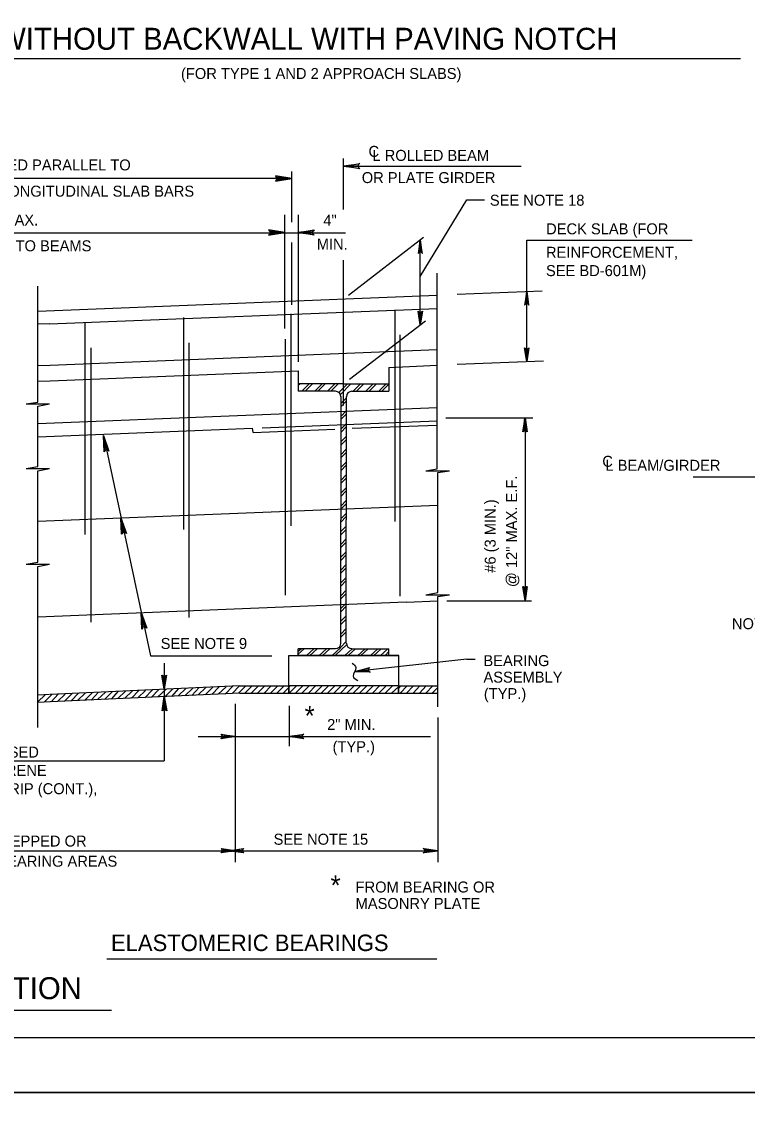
# Model space of a CAD drawing. Extents: x 640009 to 641706, y 298547 to 299735.
# Drawn here: x 640263.3 to 640461.6, y 299133.7 to 299433.7 of the extents above; entities that cross this region are included whole.
import ezdxf

# ---------------------------------------------------------------- set-up
doc = ezdxf.new("R2010")
doc.units = 0
doc.layers.add('1', color=7, linetype='Continuous')
doc.layers.add('PLT-BNDY', color=7, linetype='Continuous')

msp = doc.modelspace()

# ---------------------------------------------------------------- linework, layer by layer
at = {"layer": '1'}
for p, q in [((640254.55, 299423.68), (640459.83, 299423.68)), ((640351.28, 299382.42), (640351.28, 299396.36)), ((640337.03, 299392.84), (640337.03, 299379)), ((640351.28, 299394.31), (640399.81, 299394.31)), ((640191.28, 299390.99), (640337.03, 299390.99)), ((640372.25, 299364.12), (640385.01, 299385.07)), ((640385.01, 299385.07), (640389.78, 299385.07)), ((640335.15, 299380.98), (640335.15, 299349.93)), ((640338.9, 299380.98), (640338.9, 299340.83)), ((640169.89, 299376.11), (640351.8, 299376.11)), ((640352.59, 299359.04), (640373.15, 299374.87)), ((640337.03, 299373.39), (640337.03, 299356.43)), ((640372.25, 299350.95), (640372.25, 299374.18)), ((640401.37, 299340.91), (640401.37, 299374.09)), ((640401.37, 299374.09), (640446.57, 299374.09)), ((640351.28, 299328.92), (640351.28, 299368.63)), ((640376.9, 299311.56), (640376.9, 299365.06)), ((640267.65, 299329.83), (640267.65, 299361.46)), ((640382.39, 299359.28), (640405.63, 299360.21)), ((640267.65, 299354.68), (640376.9, 299359.06)), ((640270.9, 299351.18), (640376.9, 299355.43)), ((640336.9, 299353.93), (640336.9, 299296.06)), ((640365.28, 299355.06), (640365.28, 299297.18)), ((640267.65, 299351.18), (640270.9, 299351.31)), ((640280.53, 299351.56), (640280.53, 299293.68)), ((640307.53, 299352.93), (640307.53, 299295.06)), ((640352.94, 299336.09), (640373.66, 299352.03)), ((640366.78, 299276.81), (640366.78, 299348.18)), ((640282.28, 299269.68), (640282.28, 299344.68)), ((640309.03, 299270.93), (640309.03, 299346.06)), ((640335.4, 299277.06), (640335.4, 299347.06)), ((640271.03, 299339.93), (640376.9, 299344.18)), ((640267.65, 299339.8), (640271.03, 299339.93)), ((640271.03, 299335.68), (640338.9, 299338.4)), ((640338.9, 299338.4), (640338.9, 299332.81)), ((640363.65, 299339.32), (640376.9, 299339.93)), ((640363.65, 299339.32), (640363.65, 299332.81)), ((640382.39, 299340.15), (640405.99, 299341.1)), ((640267.65, 299335.55), (640271.03, 299335.68)), ((640351.28, 299334.81), (640338.9, 299334.81)), ((640351.28, 299334.81), (640338.9, 299334.81)), ((640338.9, 299334.81), (640338.9, 299333.81)), ((640351.28, 299334.81), (640338.9, 299334.81)), ((640338.9, 299334.81), (640338.9, 299332.81)), ((640349.03, 299332.81), (640338.9, 299332.81)), ((640349.03, 299332.81), (640338.9, 299332.81)), ((640351.28, 299334.81), (640363.65, 299334.81)), ((640351.28, 299334.81), (640363.65, 299334.81)), ((640351.28, 299334.81), (640363.65, 299334.81)), ((640353.53, 299332.81), (640363.65, 299332.81)), ((640353.53, 299332.81), (640363.65, 299332.81)), ((640363.65, 299334.81), (640363.65, 299333.81)), ((640363.65, 299334.81), (640363.65, 299332.81)), ((640264.53, 299329.33), (640267.65, 299329.83)), ((640264.53, 299329.33), (640270.9, 299329.33)), ((640267.65, 299328.68), (640270.9, 299329.33)), ((640267.78, 299329.33), (640267.78, 299329.33)), ((640350.53, 299331.31), (640350.53, 299297.68)), ((640350.53, 299331.31), (640350.53, 299297.68)), ((640352.03, 299331.31), (640352.03, 299297.68)), ((640352.03, 299331.31), (640352.03, 299297.68)), ((640267.65, 299320.36), (640267.65, 299328.68)), ((640267.65, 299323.98), (640376.9, 299328.36)), ((640329.03, 299322.81), (640376.9, 299324.68)), ((640353.65, 299322.68), (640376.9, 299323.56)), ((640379.28, 299325.56), (640403.03, 299325.56)), ((640400.9, 299325.56), (640400.9, 299275.56)), ((640267.65, 299320.36), (640326.4, 299322.68)), ((640267.65, 299312.19), (640267.65, 299320.36)), ((640285.61, 299320.74), (640298.47, 299260.46)), ((640326.53, 299321.56), (640326.4, 299322.68)), ((640326.53, 299321.56), (640348.9, 299322.43)), ((640264.53, 299311.69), (640267.65, 299312.19)), ((640264.53, 299311.69), (640270.9, 299311.69)), ((640267.65, 299311.04), (640270.9, 299311.69)), ((640267.78, 299311.69), (640267.78, 299311.69)), ((640373.78, 299311.06), (640376.9, 299311.56)), ((640267.65, 299286.06), (640267.65, 299311.04)), ((640373.78, 299311.06), (640380.28, 299311.06)), ((640377.03, 299310.56), (640380.28, 299311.06)), ((640377.03, 299311.06), (640377.03, 299311.06)), ((640377.03, 299277.81), (640377.03, 299310.56)), ((640446.9, 299309.42), (640496.46, 299309.42)), ((640267.65, 299297.33), (640377.03, 299301.68)), ((640350.53, 299263.93), (640350.53, 299297.68)), ((640350.53, 299263.93), (640350.53, 299297.68)), ((640352.03, 299263.93), (640352.03, 299297.68)), ((640352.03, 299263.93), (640352.03, 299297.68)), ((640264.53, 299285.56), (640267.65, 299286.06)), ((640264.53, 299285.56), (640270.9, 299285.56)), ((640267.65, 299284.91), (640270.9, 299285.56)), ((640267.65, 299240.93), (640267.65, 299284.91)), ((640267.78, 299285.56), (640267.78, 299285.56)), ((640267.65, 299271.18), (640368.4, 299275.25)), ((640368.4, 299275.18), (640377.03, 299275.56)), ((640373.78, 299277.18), (640377.03, 299277.81)), ((640373.78, 299277.18), (640380.28, 299277.18)), ((640377.03, 299276.68), (640380.28, 299277.18)), ((640377.03, 299246.56), (640377.03, 299276.68)), ((640379.53, 299275.56), (640402.65, 299275.56)), ((640298.47, 299260.46), (640331.68, 299260.46)), ((640336.28, 299250.31), (640336.28, 299260.56)), ((640336.28, 299260.56), (640366.4, 299260.56)), ((640349.03, 299262.43), (640338.9, 299262.43)), ((640338.9, 299260.56), (640338.9, 299262.43)), ((640349.03, 299262.43), (640338.9, 299262.43)), ((640338.9, 299260.56), (640338.9, 299262.43)), ((640366.4, 299260.56), (640338.9, 299260.56)), ((640351.28, 299260.56), (640338.9, 299260.56)), ((640351.28, 299260.56), (640363.65, 299260.56)), ((640353.53, 299262.43), (640363.65, 299262.43)), ((640353.53, 299262.43), (640363.65, 299262.43)), ((640363.65, 299260.56), (640363.65, 299262.43)), ((640363.65, 299260.56), (640363.65, 299262.43)), ((640366.4, 299250.31), (640366.4, 299260.56)), ((640302.25, 299258.47), (640302.25, 299231.8)), ((640385.03, 299259.56), (640354.54, 299256.23)), ((640385.03, 299259.56), (640387.28, 299259.56)), ((640322.78, 299252.31), (640271.03, 299249.93)), ((640322.9, 299252.31), (640336.28, 299252.31)), ((640366.4, 299252.31), (640376.9, 299252.31)), ((640270.9, 299249.93), (640267.65, 299249.79)), ((640322.9, 299250.31), (640271.03, 299247.93)), ((640322.9, 299250.31), (640336.28, 299250.31)), ((640336.28, 299250.31), (640366.4, 299250.31)), ((640336.28, 299250.31), (640366.28, 299250.31)), ((640366.4, 299250.31), (640376.9, 299250.31)), ((640271.03, 299247.93), (640267.65, 299247.78)), ((640321.65, 299247.43), (640321.65, 299204.09)), ((640336.4, 299246.81), (640336.4, 299235.81)), ((640377.03, 299243.68), (640377.03, 299204.09)), ((640311.53, 299238.43), (640339.15, 299238.43)), ((640336.15, 299238.43), (640375.04, 299238.43)), ((640227.64, 299231.8), (640302.25, 299231.8)), ((640200.03, 299207.26), (640321.65, 299207.26)), ((640321.65, 299207.26), (640377.03, 299207.26)), ((640286.55, 299177.75), (640376.81, 299177.75)), ((640232.63, 299163.7), (640287.78, 299163.7)), ((640835.47, 299156.17), (640049.47, 299156.17)), ((640835.47, 299156.17), (640049.47, 299156.17))]:
    msp.add_line(p, q, dxfattribs=at)
for points in [[(640355.52, 299393.77), (640355.35, 299394.09), (640351.28, 299394.31), (640355.52, 299393.77), (640355.73, 299393.58), (640351.28, 299394.31), (640355.35, 299394.51), (640355.5, 299394.81), (640351.28, 299394.31), (640355.73, 299395.03), (640355.5, 299394.81)], [(640332.86, 299390.34), (640333.04, 299390.66), (640337.11, 299390.88), (640332.86, 299390.34), (640332.65, 299390.16), (640337.11, 299390.88), (640333.04, 299391.08), (640332.88, 299391.38), (640337.11, 299390.88), (640332.65, 299391.61), (640332.88, 299391.38)], [(640330.99, 299375.59), (640331.16, 299375.91), (640335.23, 299376.13), (640330.99, 299375.59), (640330.78, 299375.41), (640335.23, 299376.13), (640331.16, 299376.33), (640331.01, 299376.63), (640335.23, 299376.13), (640330.78, 299376.86), (640331.01, 299376.63)], [(640343.07, 299375.59), (640342.89, 299375.91), (640338.82, 299376.13), (640343.07, 299375.59), (640343.28, 299375.41), (640338.82, 299376.13), (640342.89, 299376.33), (640343.05, 299376.63), (640338.82, 299376.13), (640343.28, 299376.86), (640343.05, 299376.63)], [(640372.7, 299370.64), (640372.44, 299370.79), (640372.25, 299374.18), (640372.7, 299370.64), (640372.86, 299370.46), (640372.25, 299374.18), (640372.09, 299370.79), (640371.84, 299370.65), (640372.25, 299374.18), (640371.65, 299370.46), (640371.84, 299370.65)], [(640401.82, 299356.5), (640401.56, 299356.65), (640401.37, 299360.04), (640401.82, 299356.5), (640401.98, 299356.33), (640401.37, 299360.04), (640401.21, 299356.65), (640400.95, 299356.52), (640401.37, 299360.04), (640400.77, 299356.33), (640400.95, 299356.52)], [(640372.7, 299354.49), (640372.44, 299354.34), (640372.25, 299350.95), (640372.7, 299354.49), (640372.86, 299354.67), (640372.25, 299350.95), (640372.09, 299354.34), (640371.84, 299354.48), (640372.25, 299350.95), (640371.65, 299354.67), (640371.84, 299354.48)], [(640401.82, 299344.45), (640401.56, 299344.3), (640401.37, 299340.91), (640401.82, 299344.45), (640401.98, 299344.62), (640401.37, 299340.91), (640401.21, 299344.3), (640400.95, 299344.43), (640401.37, 299340.91), (640400.77, 299344.62), (640400.95, 299344.43)], [(640338.9, 299334.43), (640339.28, 299334.81)], [(640339.9, 299332.81), (640341.9, 299334.81)], [(640340.78, 299332.81), (640342.78, 299334.81)], [(640343.4, 299332.81), (640345.4, 299334.81)], [(640344.28, 299332.81), (640346.28, 299334.81)], [(640346.9, 299332.81), (640348.9, 299334.81)], [(640347.78, 299332.81), (640349.78, 299334.81)], [(640350.03, 299332.43), (640352.4, 299334.81)], [(640350.4, 299331.93), (640353.28, 299334.81)], [(640353.9, 299332.81), (640355.9, 299334.81)], [(640354.78, 299332.81), (640356.78, 299334.81)], [(640357.4, 299332.81), (640359.4, 299334.81)], [(640358.28, 299332.81), (640360.28, 299334.81)], [(640360.9, 299332.81), (640362.9, 299334.81)], [(640361.78, 299332.81), (640363.65, 299334.68)], [(640363.53, 299332.81), (640363.65, 299332.93)], [(640350.53, 299329.43), (640352.03, 299330.93)], [(640350.53, 299328.56), (640352.03, 299330.06)], [(640350.53, 299325.93), (640352.03, 299327.43)], [(640350.53, 299325.06), (640352.03, 299326.56)], [(640350.53, 299322.43), (640352.03, 299323.93)], [(640400.4, 299321.81), (640400.78, 299321.93), (640400.9, 299325.56), (640400.4, 299321.81), (640400.28, 299321.68), (640400.9, 299325.56), (640401.15, 299321.93), (640401.4, 299321.81), (640400.9, 299325.56), (640401.53, 299321.68), (640401.4, 299321.81)], [(640401.34, 299321.98), (640401.07, 299322.13), (640400.89, 299325.52), (640401.34, 299321.98), (640401.49, 299321.81), (640400.89, 299325.52), (640400.72, 299322.13), (640400.47, 299322), (640400.89, 299325.52), (640400.29, 299321.81), (640400.47, 299322)], [(640285.99, 299316.43), (640286.18, 299316.61), (640285.61, 299320.74), (640285.99, 299316.43), (640285.8, 299316.24), (640285.61, 299320.74), (640286.55, 299316.8), (640286.93, 299316.61), (640285.61, 299320.74), (640287.11, 299316.43), (640286.93, 299316.61)], [(640350.53, 299321.56), (640352.03, 299323.06)], [(640350.53, 299318.93), (640352.03, 299320.43)], [(640350.53, 299318.06), (640352.03, 299319.56)], [(640350.53, 299315.43), (640352.03, 299316.93)], [(640350.53, 299314.56), (640352.03, 299316.06)], [(640350.53, 299311.93), (640352.03, 299313.43)], [(640350.53, 299311.06), (640352.03, 299312.56)], [(640350.53, 299308.43), (640352.03, 299309.93)], [(640350.53, 299307.56), (640352.03, 299309.06)], [(640350.53, 299304.93), (640352.03, 299306.43)], [(640350.53, 299304.06), (640352.03, 299305.56)], [(640350.53, 299301.43), (640352.03, 299302.93)], [(640350.53, 299300.56), (640352.03, 299302.06)], [(640350.53, 299297.93), (640352.03, 299299.43)], [(640290.78, 299293.92), (640290.97, 299294.11), (640290.41, 299298.24), (640290.78, 299293.92), (640290.6, 299293.74), (640290.41, 299298.24), (640291.35, 299294.3), (640291.72, 299294.11), (640290.41, 299298.24), (640291.91, 299293.92), (640291.72, 299294.11)], [(640350.53, 299297.06), (640352.03, 299298.56)], [(640350.53, 299294.43), (640352.03, 299295.93)], [(640350.53, 299293.56), (640352.03, 299295.06)], [(640350.53, 299290.93), (640352.03, 299292.43)], [(640350.53, 299290.06), (640352.03, 299291.56)], [(640350.53, 299287.43), (640352.03, 299288.93)], [(640350.53, 299286.56), (640352.03, 299288.06)], [(640350.53, 299283.93), (640352.03, 299285.43)], [(640350.53, 299283.06), (640352.03, 299284.56)], [(640350.53, 299280.43), (640352.03, 299281.93)], [(640350.53, 299279.56), (640352.03, 299281.06)], [(640350.53, 299276.93), (640352.03, 299278.43)], [(640401.4, 299279.31), (640401.15, 299279.18), (640400.9, 299275.56), (640401.4, 299279.31), (640401.53, 299279.43), (640400.9, 299275.56), (640400.78, 299279.18), (640400.53, 299279.31), (640400.9, 299275.56), (640400.28, 299279.43), (640400.53, 299279.31)], [(640350.53, 299276.06), (640352.03, 299277.56)], [(640296.32, 299268.02), (640296.5, 299268.2), (640295.94, 299272.33), (640296.32, 299268.02), (640296.13, 299267.83), (640295.94, 299272.33), (640296.88, 299268.39), (640297.25, 299268.2), (640295.94, 299272.33), (640297.44, 299268.02), (640297.25, 299268.2)], [(640350.53, 299273.43), (640352.03, 299274.93)], [(640350.53, 299272.56), (640352.03, 299274.06)], [(640350.53, 299269.93), (640352.03, 299271.43)], [(640350.53, 299269.06), (640352.03, 299270.56)], [(640350.53, 299266.43), (640352.03, 299267.93)], [(640350.53, 299265.56), (640352.03, 299267.06)], [(640349.03, 299260.56), (640352.15, 299263.56)], [(640350.4, 299262.81), (640352.03, 299264.43)], [(640338.9, 299260.93), (640340.53, 299262.43)], [(640338.9, 299261.81), (640339.65, 299262.43)], [(640341.15, 299260.56), (640343.15, 299262.43)], [(640342.03, 299260.56), (640344.03, 299262.43)], [(640344.65, 299260.56), (640346.65, 299262.43)], [(640345.53, 299260.56), (640347.53, 299262.43)], [(640348.15, 299260.56), (640350.4, 299262.68)], [(640351.65, 299260.56), (640353.65, 299262.43)], [(640352.53, 299260.56), (640354.53, 299262.43)], [(640355.15, 299260.56), (640357.15, 299262.43)], [(640356.03, 299260.56), (640358.03, 299262.43)], [(640358.65, 299260.56), (640360.65, 299262.43)], [(640359.53, 299260.56), (640361.53, 299262.43)], [(640361.4, 299260.56), (640363.4, 299262.43)], [(640362.65, 299260.56), (640363.65, 299261.68)], [(640358.29, 299256.16), (640358.19, 299256.42), (640354.54, 299256.23), (640358.29, 299256.16), (640358.53, 299256.02), (640354.54, 299256.23), (640358.1, 299256.81), (640358.25, 299257.17), (640354.54, 299256.23), (640358.39, 299257.29), (640358.25, 299257.17)], [(640302.71, 299255.12), (640302.46, 299254.99), (640302.25, 299251.36), (640302.71, 299255.12), (640302.83, 299255.25), (640302.25, 299251.36), (640302.08, 299254.99), (640301.83, 299255.11), (640302.25, 299251.36), (640301.58, 299255.23), (640301.83, 299255.11)], [(640298.78, 299249.18), (640300.78, 299251.31)], [(640300.53, 299249.31), (640302.65, 299251.31)], [(640302.4, 299249.31), (640304.53, 299251.43)], [(640304.28, 299249.43), (640306.28, 299251.56)], [(640306.03, 299249.56), (640308.15, 299251.56)], [(640307.9, 299249.56), (640310.03, 299251.68)], [(640309.78, 299249.68), (640311.78, 299251.81)], [(640311.53, 299249.81), (640313.65, 299251.81)], [(640313.4, 299249.81), (640315.53, 299251.93)], [(640315.28, 299249.93), (640317.28, 299252.06)], [(640317.03, 299250.06), (640319.15, 299252.06)], [(640318.9, 299250.06), (640321.03, 299252.18)], [(640320.78, 299250.18), (640322.78, 299252.31)], [(640322.53, 299250.31), (640324.53, 299252.31)], [(640324.28, 299250.31), (640326.28, 299252.31)], [(640326.03, 299250.31), (640328.03, 299252.31)], [(640327.78, 299250.31), (640329.78, 299252.31)], [(640329.53, 299250.31), (640331.53, 299252.31)], [(640331.28, 299250.31), (640333.28, 299252.31)], [(640333.03, 299250.31), (640335.03, 299252.31)], [(640334.78, 299250.31), (640336.28, 299251.81)], [(640336.28, 299251.93), (640336.65, 299252.31)], [(640336.4, 299250.31), (640338.4, 299252.31)], [(640338.15, 299250.31), (640340.15, 299252.31)], [(640339.9, 299250.31), (640341.9, 299252.31)], [(640341.65, 299250.31), (640343.65, 299252.31)], [(640343.4, 299250.31), (640345.4, 299252.31)], [(640345.15, 299250.31), (640347.15, 299252.31)], [(640346.9, 299250.31), (640348.9, 299252.31)], [(640348.65, 299250.31), (640350.65, 299252.31)], [(640350.4, 299250.31), (640352.4, 299252.31)], [(640352.15, 299250.31), (640354.15, 299252.31)], [(640353.9, 299250.31), (640355.9, 299252.31)], [(640355.65, 299250.31), (640357.65, 299252.31)], [(640357.4, 299250.31), (640359.4, 299252.31)], [(640359.15, 299250.31), (640361.15, 299252.31)], [(640360.9, 299250.31), (640362.9, 299252.31)], [(640362.65, 299250.31), (640364.65, 299252.31)], [(640364.4, 299250.31), (640366.28, 299252.06)], [(640366.4, 299251.68), (640366.9, 299252.31)], [(640366.78, 299250.31), (640368.65, 299252.31)], [(640368.53, 299250.31), (640370.4, 299252.31)], [(640370.28, 299250.31), (640372.15, 299252.31)], [(640372.03, 299250.31), (640373.9, 299252.31)], [(640373.78, 299250.31), (640375.65, 299252.31)], [(640375.53, 299250.31), (640376.9, 299251.68)], [(640267.65, 299247.92), (640269.65, 299249.81)], [(640267.65, 299249.67), (640267.78, 299249.81)], [(640269.4, 299247.81), (640271.53, 299249.93)], [(640271.28, 299247.93), (640273.28, 299250.06)], [(640273.03, 299248.06), (640275.15, 299250.06)], [(640274.9, 299248.06), (640277.03, 299250.18)], [(640276.78, 299248.18), (640278.78, 299250.31)], [(640278.53, 299248.31), (640280.65, 299250.31)], [(640280.4, 299248.31), (640282.53, 299250.43)], [(640282.28, 299248.43), (640284.28, 299250.56)], [(640284.03, 299248.56), (640286.15, 299250.56)], [(640285.9, 299248.56), (640288.03, 299250.68)], [(640287.78, 299248.68), (640289.78, 299250.81)], [(640289.53, 299248.81), (640291.65, 299250.81)], [(640291.4, 299248.81), (640293.53, 299250.93)], [(640293.28, 299248.93), (640295.28, 299251.06)], [(640295.03, 299249.06), (640297.15, 299251.06)], [(640296.9, 299249.06), (640299.03, 299251.18)], [(640301.83, 299245.6), (640302.07, 299245.73), (640302.25, 299249.36), (640301.83, 299245.6), (640301.7, 299245.47), (640302.25, 299249.36), (640302.45, 299245.74), (640302.7, 299245.62), (640302.25, 299249.36), (640302.95, 299245.5), (640302.7, 299245.62)], [(640366.15, 299250.31), (640366.28, 299250.31)], [(640317.9, 299238.93), (640318.03, 299238.68), (640321.65, 299238.43), (640317.9, 299238.93), (640317.78, 299239.06), (640321.65, 299238.43), (640318.03, 299238.31), (640317.9, 299238.06), (640321.65, 299238.43), (640317.78, 299237.81), (640317.9, 299238.06)], [(640340.15, 299238.06), (640340.03, 299238.31), (640336.4, 299238.43), (640340.15, 299238.06), (640340.4, 299237.81), (640336.4, 299238.43), (640340.03, 299238.68), (640340.15, 299238.93), (640336.4, 299238.43), (640340.4, 299239.06), (640340.15, 299238.93)], [(640317.9, 299207.76), (640318.03, 299207.51), (640321.65, 299207.26), (640317.9, 299207.76), (640317.78, 299207.89), (640321.65, 299207.26), (640318.03, 299207.14), (640317.9, 299206.89), (640321.65, 299207.26), (640317.78, 299206.64), (640317.9, 299206.89)], [(640323.9, 299206.76), (640323.78, 299207.01), (640320.15, 299207.26), (640323.9, 299206.76), (640324.03, 299206.64), (640320.15, 299207.26), (640323.65, 299207.39), (640323.9, 299207.76), (640320.15, 299207.26), (640324.03, 299207.89), (640323.9, 299207.76)], [(640373.28, 299207.76), (640373.4, 299207.51), (640377.03, 299207.26), (640373.28, 299207.76), (640373.03, 299207.89), (640377.03, 299207.26), (640373.4, 299207.14), (640373.28, 299206.76), (640377.03, 299207.26), (640373.03, 299206.64), (640373.28, 299206.76)]]:
    msp.add_lwpolyline(points, dxfattribs=at)
msp.add_lwpolyline([(640336.28, 299252.31), (640336.28, 299250.31), (640366.28, 299250.31), (640366.28, 299252.31)], close=True, dxfattribs=at)
for centre, start, end in [((640349.08, 299331.28), 0, 90), ((640349.08, 299331.28), 0, 90), ((640353.54, 299331.28), 90, 180), ((640353.54, 299331.28), 90, 180), ((640349.08, 299263.96), 270, 0), ((640349.08, 299263.96), 270, 0), ((640353.54, 299263.96), 180, 270), ((640353.54, 299263.96), 180, 270)]:
    msp.add_arc(centre, 1.49, start, end, dxfattribs=at)
msp.add_spline([(640353.66, 299258.47), (640354.65, 299257.3), (640353.88, 299254.93), (640355.16, 299253.75)], degree=3, dxfattribs=at)
at = {"layer": 'PLT-BNDY'}
for points in [[(640009.47, 299735.17), (640850.47, 299735.17), (640850.47, 299141.17), (640009.47, 299141.17)], [(640009.47, 299141.17), (640850.47, 299141.17), (640850.47, 298547.17), (640009.47, 298547.17)]]:
    msp.add_lwpolyline(points, close=True, dxfattribs=at)

# ---------------------------------------------------------------- texts
at = {"layer": '1'}
for s, height, rotation, p in [('WITHOUT BACKWALL WITH PAVING NOTCH', 6, 360, (640256.81, 299426.09)), ('@ 12" MAX. E.F.', 3, 90, (640398.74, 299279.28)), ('#6 (3 MIN.)', 3, 90, (640392.88, 299283.2))]:
    msp.add_text(s, height=height, rotation=rotation, dxfattribs=at).set_placement(p)
for s, height, p in [('(FOR TYPE 1 AND 2 APPROACH SLABS)', 3, (640306.83, 299418.1)), ('C', 3, (640358.11, 299396.82)), ('L ROLLED BEAM', 3, (640359.19, 299395.73)), ('#4 @ 9" MAX. L-BARS PLACED PARALLEL TO', 3, (640206.87, 299393.13)), ('OR PLATE GIRDER', 3, (640356.26, 299389.66)), ('AND CENTERED BETWEEN TOP LONGITUDINAL SLAB BARS', 3, (640194.29, 299385.95)), ('SEE NOTE 18', 3, (640391.29, 299383.48)), ('#4 TIES @ 9" MAX.', 3, (640232.41, 299378.07)), ('4"', 3, (640345.75, 299378)), ('DECK SLAB (FOR', 3, (640406.67, 299375.66)), ('MIN.', 3, (640343.95, 299371.49)), ('PLACED PARALLEL TO BEAMS', 3, (640223.02, 299371.03)), ('REINFORCEMENT,', 3, (640406.64, 299369.25)), ('SEE BD-601M)', 3, (640406.64, 299364.25)), ('C', 3, (640422.04, 299312.15)), ('L BEAM/GIRDER', 3, (640422.91, 299311.06)), ('NOTE: CLIP TOP AND BOTTOM FLANGES', 3, (640457.49, 299267.78)), ('SEE NOTE 9', 3, (640301.27, 299262.38)), ('BEARING', 3, (640389.53, 299257.68)), ('ASSEMBLY', 3, (640389.53, 299253.18)), ('(TYP.)', 3, (640389.65, 299248.68)), ('*', 5.35, (640340.62, 299241.46)), ('2" MIN.', 3, (640346.78, 299240.24)), ('(TYP.)', 3, (640348.28, 299234.18)), ('1" THK. CLOSED', 3, (640236.45, 299232.7)), ('CELL NEOPRENE', 3, (640236.45, 299227.7)), ('SPONGE STRIP (CONT.),', 3, (640236.45, 299222.7)), ('BRIDGE SEAT-STEPPED OR', 3, (640226.85, 299208.39)), ('SEE NOTE 15', 3, (640332.15, 299208.89)), ('SLOPED BETWEEN BEARING AREAS', 3, (640218.28, 299202.89)), ('*', 5.35, (640347.71, 299195.14)), ('FROM BEARING OR', 3, (640354.57, 299195.84)), ('MASONRY PLATE', 3, (640354.57, 299191.34)), ('ELASTOMERIC BEARINGS', 4.5, (640287.68, 299179.84)), ('ELEVATION', 6, (640234.69, 299166.7))]:
    msp.add_text(s, height=height, dxfattribs=at).set_placement(p)

doc.saveas('drawing.dxf')
